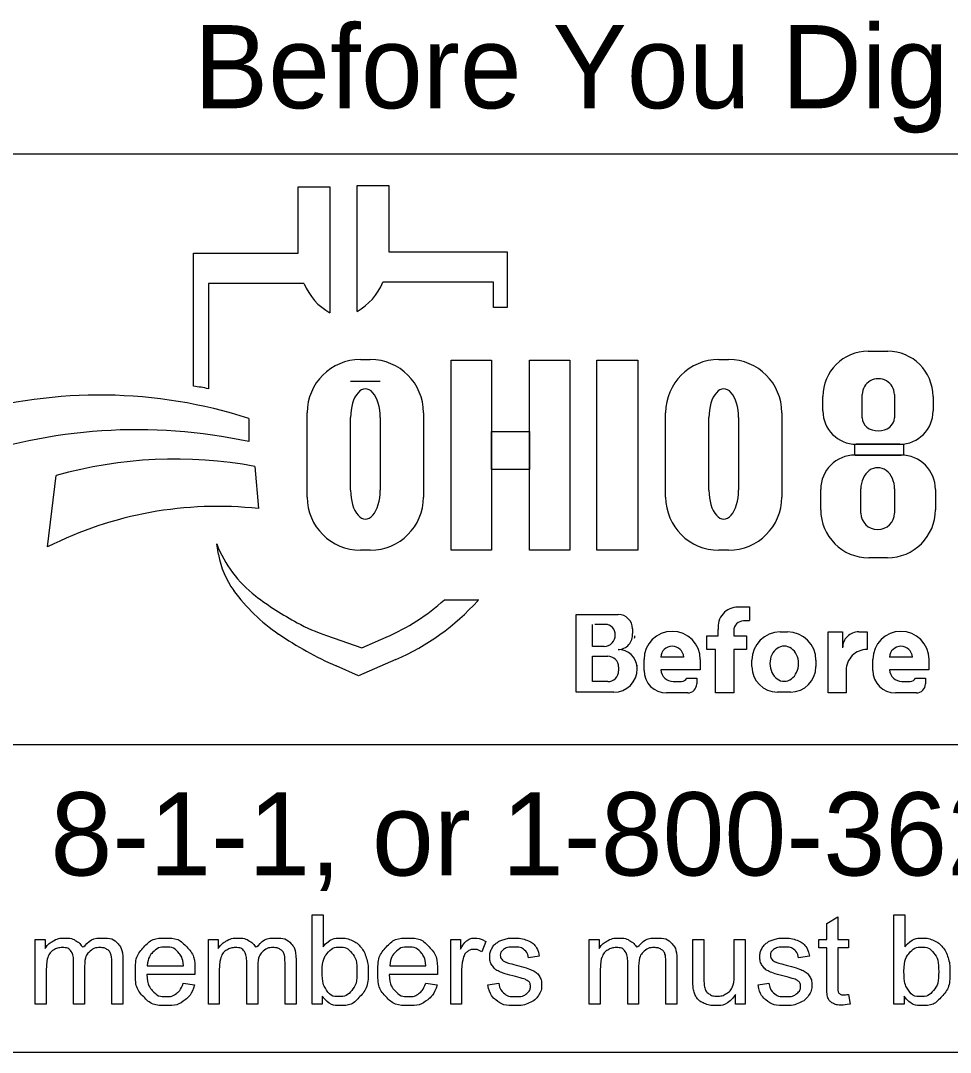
# Model space of a CAD drawing. Extents: x 0 to 34, y 0 to 22.
# Drawn here: x 3.267 to 4.831, y 2.143 to 3.88 of the extents above; entities that cross this region are included whole.
import ezdxf

# ---------------------------------------------------------------- set-up
doc = ezdxf.new("R2010")
doc.units = 0
doc.layers.add('SH_Data', color=7, linetype='Continuous')
doc.layers.add('SH_Text', color=7, linetype='Continuous')

msp = doc.modelspace()

# ---------------------------------------------------------------- linework, layer by layer
at = {"layer": 'SH_Data'}
for p, q in [((2.3775, 3.6553), (6.6275, 3.6553)), ((6.6275, 2.6607), (2.3775, 2.6607)), ((6.6275, 2.1428), (2.3775, 2.1428))]:
    msp.add_line(p, q, dxfattribs=at)
at = {"layer": 'SH_Text'}
for p, q in [((3.7335, 3.4883), (3.7335, 3.5998)), ((3.7335, 3.5998), (3.7872, 3.5998)), ((3.7872, 3.5998), (3.7872, 3.3877)), ((3.8329, 3.39), (3.8329, 3.6021)), ((3.8329, 3.6021), (3.8865, 3.6021)), ((3.8865, 3.6021), (3.8865, 3.4906)), ((3.5576, 3.2644), (3.5576, 3.4883)), ((3.5576, 3.4883), (3.7335, 3.4883)), ((3.8865, 3.4906), (4.0857, 3.4906)), ((4.0857, 3.4906), (4.0857, 3.3968)), ((4.0625, 3.4392), (3.8761, 3.4392)), ((4.0625, 3.3968), (4.0625, 3.4392)), ((3.5828, 3.4369), (3.5828, 3.26)), ((3.7439, 3.4369), (3.5828, 3.4369)), ((4.0857, 3.3968), (4.0625, 3.3968)), ((4.6931, 3.3231), (4.7258, 3.3231)), ((3.8385, 3.3091), (3.8551, 3.3091)), ((4.4416, 3.3091), (4.4581, 3.3091)), ((3.8718, 3.2721), (3.822, 3.2721)), ((4.683, 3.2111), (4.683, 3.2504)), ((4.7371, 3.2504), (4.7371, 3.2111)), ((4.6168, 3.2225), (4.6168, 3.2468)), ((4.8022, 3.2468), (4.8022, 3.2225)), ((3.7491, 3.0776), (3.7491, 3.2196)), ((3.9445, 3.2196), (3.9445, 3.0776)), ((4.3521, 3.0776), (4.3521, 3.2196)), ((4.5476, 3.2196), (4.5476, 3.0776)), ((3.6509, 3.2097), (3.6509, 3.1709)), ((3.822, 3.089), (3.822, 3.2114)), ((3.8718, 3.2114), (3.8718, 3.089)), ((4.425, 3.089), (4.425, 3.2114)), ((4.4748, 3.2114), (4.4748, 3.089)), ((4.7462, 3.1665), (4.6728, 3.1665)), ((4.671, 3.1482), (4.7483, 3.1482)), ((3.6608, 3.1291), (3.6671, 3.0582)), ((3.312, 2.9936), (3.3267, 3.1137)), ((4.6131, 3.0563), (4.6131, 3.0903)), ((4.6806, 3.0503), (4.6806, 3.0912)), ((4.7374, 3.0912), (4.7374, 3.0503)), ((4.8062, 3.0903), (4.8062, 3.0563)), ((3.5997, 2.9807), (3.5967, 2.9986)), ((3.8551, 2.9882), (3.8385, 2.9882)), ((4.4581, 2.9882), (4.4416, 2.9882)), ((4.7252, 2.9753), (4.6941, 2.9753)), ((3.98, 2.9048), (4.0375, 2.9048)), ((4.4739, 2.8926), (4.4934, 2.8926)), ((4.4934, 2.8926), (4.4934, 2.8696)), ((4.2013, 2.749), (4.2013, 2.8798)), ((4.2013, 2.8798), (4.2725, 2.8798)), ((4.4934, 2.8691), (4.4832, 2.8691)), ((4.2293, 2.8263), (4.2293, 2.8632)), ((4.2545, 2.8632), (4.2332, 2.8632)), ((4.2963, 2.856), (4.2963, 2.8481)), ((4.4406, 2.8442), (4.4406, 2.8546)), ((4.4667, 2.8526), (4.4667, 2.8442)), ((4.5451, 2.8508), (4.5573, 2.8508)), ((4.6254, 2.7478), (4.6254, 2.8505)), ((4.6254, 2.8505), (4.6499, 2.8505)), ((4.6499, 2.8505), (4.6499, 2.8237)), ((4.6772, 2.8505), (4.691, 2.8505)), ((4.691, 2.8505), (4.691, 2.8209)), ((3.7816, 2.8444), (3.841, 2.8239)), ((3.841, 2.8239), (3.8821, 2.8417)), ((4.4213, 2.8212), (4.4213, 2.8442)), ((4.4213, 2.8442), (4.4406, 2.8442)), ((4.4667, 2.8442), (4.4883, 2.8442)), ((4.4883, 2.8442), (4.4883, 2.8212)), ((4.2487, 2.8263), (4.2293, 2.8263)), ((4.4362, 2.8212), (4.4213, 2.8212)), ((4.4362, 2.7478), (4.4362, 2.8212)), ((4.4883, 2.8212), (4.4667, 2.8212)), ((4.4667, 2.8212), (4.4667, 2.7478)), ((3.8983, 2.8044), (3.835, 2.7769)), ((4.2293, 2.7669), (4.2293, 2.8097)), ((4.2293, 2.8097), (4.2548, 2.8097)), ((4.3159, 2.7858), (4.3159, 2.8042)), ((4.3824, 2.8082), (4.3439, 2.8082)), ((4.4104, 2.8042), (4.4104, 2.7866)), ((4.4973, 2.7922), (4.4973, 2.8029)), ((4.6051, 2.8029), (4.6051, 2.7922)), ((4.7008, 2.7858), (4.7008, 2.8042)), ((4.7674, 2.8082), (4.7288, 2.8082)), ((4.7953, 2.8042), (4.7953, 2.7866)), ((3.835, 2.7769), (3.7976, 2.7934)), ((4.2729, 2.7916), (4.2729, 2.7853)), ((4.3043, 2.7887), (4.3043, 2.7884)), ((4.4104, 2.7866), (4.344, 2.7866)), ((4.6559, 2.786), (4.6559, 2.7478)), ((4.7953, 2.7866), (4.7289, 2.7866)), ((4.2546, 2.7669), (4.2293, 2.7669)), ((4.3649, 2.7673), (4.379, 2.7673)), ((4.3876, 2.7729), (4.4045, 2.7729)), ((4.4045, 2.7729), (4.4045, 2.7631)), ((4.7498, 2.7673), (4.7639, 2.7673)), ((4.7725, 2.7729), (4.7894, 2.7729)), ((4.7894, 2.7729), (4.7894, 2.7631)), ((4.265, 2.749), (4.2013, 2.749)), ((4.3892, 2.7478), (4.3538, 2.7478)), ((4.4667, 2.7478), (4.4362, 2.7478)), ((4.5623, 2.7494), (4.5401, 2.7494)), ((4.6559, 2.7478), (4.6254, 2.7478)), ((4.7742, 2.7478), (4.7388, 2.7478))]:
    msp.add_line(p, q, dxfattribs=at)
for points in [[(3.991, 3.3081), (4.0589, 3.3081), (4.0589, 2.9881), (3.991, 2.9881)], [(4.1231, 3.3081), (4.1911, 3.3081), (4.1911, 2.9881), (4.1231, 2.9881)], [(4.2364, 3.3081), (4.3052, 3.3081), (4.3052, 2.9881), (4.2364, 2.9881)], [(4.0589, 3.1882), (4.1231, 3.1882), (4.1231, 3.1242), (4.0589, 3.1242)], [(4.6706, 3.1665), (4.7523, 3.1665), (4.7523, 3.1481), (4.6706, 3.1481)]]:
    msp.add_lwpolyline(points, close=True, dxfattribs=at)
for points in [[(3.7743, 2.2239), (3.7573, 2.2239), (3.7573, 2.3741), (3.7757, 2.3741), (3.7757, 2.3206)], [(4.6233, 2.2558), (4.6233, 2.3185), (4.6097, 2.3185), (4.6097, 2.3328), (4.6233, 2.3328), (4.6233, 2.3597), (4.6417, 2.3708), (4.6417, 2.3328), (4.6601, 2.3328), (4.6601, 2.3185), (4.6417, 2.3185), (4.6417, 2.2547)], [(4.7534, 2.2239), (4.7363, 2.2239), (4.7363, 2.3741), (4.7548, 2.3741), (4.7548, 2.3206)], [(3.2912, 2.2239), (3.2912, 2.3328), (3.3077, 2.3328), (3.3077, 2.3174)], [(3.5826, 2.2239), (3.5826, 2.3328), (3.5991, 2.3328), (3.5991, 2.3174)], [(3.9904, 2.2239), (3.9904, 2.3328), (4.007, 2.3328), (4.007, 2.3163)], [(4.0495, 2.3293), (4.043, 2.3122)], [(4.2236, 2.2239), (4.2236, 2.3328), (4.2401, 2.3328), (4.2401, 2.3174)], [(4.3979, 2.2654), (4.3979, 2.3328), (4.4164, 2.3328), (4.4164, 2.2724)], [(4.4676, 2.2745), (4.4676, 2.3328), (4.4861, 2.3328), (4.4861, 2.2239), (4.4696, 2.2239)], [(3.3743, 2.2871), (3.3743, 2.2239), (3.3559, 2.2239), (3.3559, 2.2946)], [(3.4388, 2.2986), (3.4388, 2.2239), (3.4203, 2.2239), (3.4203, 2.2924)], [(3.6657, 2.2871), (3.6657, 2.2239), (3.6473, 2.2239), (3.6473, 2.2946)], [(3.7301, 2.2986), (3.7301, 2.2239), (3.7117, 2.2239), (3.7117, 2.2924)], [(4.1394, 2.3046), (4.1213, 2.3022)], [(4.3067, 2.2871), (4.3067, 2.2239), (4.2883, 2.2239), (4.2883, 2.2946)], [(4.3711, 2.2986), (4.3711, 2.2239), (4.3527, 2.2239), (4.3527, 2.2924)], [(4.594, 2.3046), (4.5759, 2.3022)], [(3.3097, 2.2803), (3.3097, 2.2239), (3.2912, 2.2239)], [(3.4799, 2.2887), (3.5406, 2.2887)], [(3.601, 2.2803), (3.601, 2.2239), (3.5826, 2.2239)], [(3.8879, 2.2887), (3.9486, 2.2887)], [(4.0088, 2.2809), (4.0088, 2.2239), (3.9904, 2.2239)], [(4.242, 2.2803), (4.242, 2.2239), (4.2236, 2.2239)], [(3.56, 2.2736), (3.4788, 2.2736)], [(3.5404, 2.2591), (3.5595, 2.2567)], [(3.968, 2.2736), (3.8868, 2.2736)], [(3.9484, 2.2591), (3.9675, 2.2567)], [(4.053, 2.2564), (4.0712, 2.2593)], [(4.5076, 2.2564), (4.5258, 2.2593)], [(3.7743, 2.2375), (3.7743, 2.2239)], [(4.4696, 2.2239), (4.4696, 2.24)], [(4.6601, 2.2404), (4.6628, 2.2241)], [(4.7534, 2.2375), (4.7534, 2.2239)]]:
    msp.add_lwpolyline(points, dxfattribs=at)
for centre, radius, start, end in [((3.7847, 3.476), 0.0985, 299.2531, 338.0704), ((3.8353, 3.4736), 0.0985, 201.9296, 240.7469), ((4.6931, 3.2468), 0.0763, 90, 180), ((4.7258, 3.2468), 0.0763, 0, 90), ((3.8385, 3.2196), 0.0895, 90, 180), ((3.8551, 3.2196), 0.0895, 0, 90), ((4.4416, 3.2196), 0.0895, 90, 180), ((4.4581, 3.2196), 0.0895, 0, 90), ((3.3997, 2.4302), 0.8191, 72.1402, 106.3144), ((3.4295, 2.4554), 0.8191, 79.2074, 81.0007), ((4.6728, 3.2225), 0.056, 180, 270), ((4.7462, 3.2225), 0.056, 270, 0), ((3.4628, 2.2991), 0.8919, 77.8238, 109.8274), ((4.671, 3.0903), 0.0579, 90, 180), ((4.7483, 3.0903), 0.0579, 0, 90), ((3.5267, 2.4094), 0.7322, 79.44, 105.8467), ((3.8385, 3.0776), 0.0895, 180, 270), ((3.8551, 3.0776), 0.0895, 270, 0), ((4.4416, 3.0776), 0.0895, 180, 270), ((4.4581, 3.0776), 0.0895, 270, 0), ((3.5987, 2.4262), 0.6357, 83.8248, 116.8021), ((4.6941, 3.0563), 0.081, 180, 270), ((4.7252, 3.0563), 0.081, 270, 0), ((3.7841, 3.0707), 0.2008, 201.0457, 232.5314), ((3.741, 3.0048), 0.1433, 189.6817, 216.0884), ((3.8747, 3.1022), 0.3088, 216.0884, 235.7167), ((3.9766, 3.3219), 0.5173, 232.5314, 241.794), ((3.7387, 3.1722), 0.3602, 293.4582, 312.0712), ((3.7387, 3.1722), 0.401, 293.4582, 317.8286), ((4.4739, 2.859), 0.0335, 90, 187.5187), ((3.8914, 3.1631), 0.3371, 241.794, 250.9821), ((4.2725, 2.856), 0.0238, 0, 90), ((4.4832, 2.8526), 0.0165, 90, 180), ((4.2505, 2.8463), 0.0169, 357.8325, 90), ((4.3631, 2.8042), 0.0473, 0, 180), ((4.5451, 2.8029), 0.0478, 90, 180), ((4.5573, 2.8029), 0.0478, 0, 90), ((4.6768, 2.8237), 0.0269, 89.2449, 180), ((4.7481, 2.8042), 0.0473, 0, 180), ((4.0412, 3.3465), 0.6044, 235.7167, 246.2325), ((4.2487, 2.845), 0.0187, 270, 2.0582), ((4.2721, 2.8453), 0.0243, 270, 6.6529), ((4.2827, 2.8438), 0.0175, 347.4023, 0), ((4.2722, 2.7889), 0.0321, 4.0748, 90), ((4.3632, 2.8072), 0.0193, 2.9632, 177.0368), ((4.6908, 2.786), 0.0349, 89.6033, 180), ((4.7481, 2.8072), 0.0193, 2.9632, 177.0368), ((4.2548, 2.7916), 0.0181, 0, 90), ((4.2546, 2.7853), 0.0184, 270, 0), ((4.265, 2.7884), 0.0393, 270, 0), ((4.2714, 2.7887), 0.033, 0, 11.7502), ((4.3538, 2.7858), 0.038, 180, 270), ((4.3649, 2.7883), 0.021, 184.827, 270), ((4.5401, 2.7922), 0.0428, 180, 270), ((4.5623, 2.7922), 0.0428, 270, 0), ((4.7388, 2.7858), 0.038, 180, 270), ((4.7498, 2.7883), 0.021, 184.827, 270), ((4.379, 2.7767), 0.00938, 270, 335.9979), ((4.3892, 2.7631), 0.0152, 270, 0), ((4.7639, 2.7767), 0.00938, 270, 335.9979), ((4.7742, 2.7631), 0.0152, 270, 0)]:
    msp.add_arc(centre, radius, start, end, dxfattribs=at)
for centre, major_axis, ratio, start_param, end_param in [((4.71, 3.2504), (0.0271, 0), 0.969373, 0, 3.141593), ((3.8469, 3.2114), (0, 0.0484), 0.514403, 4.712389, 7.853982), ((4.4499, 3.2114), (0, 0.0484), 0.514403, 4.712389, 7.853982), ((4.71, 3.2111), (0.0271, 0), 0.818453, 3.141593, 6.283185), ((4.709, 3.0912), (0, 0.0358), 0.794529, 4.712389, 7.853982), ((3.8469, 3.089), (0, 0.0484), 0.514403, 1.570796, 4.712389), ((4.4499, 3.089), (0, 0.0484), 0.514403, 1.570796, 4.712389), ((4.709, 3.0503), (0.0284, 0), 0.959837, 3.141593, 6.283185), ((4.5517, 2.7976), (0, 0.029), 0.832186, 4.712389, 7.853982), ((4.5517, 2.7976), (0, 0.0302), 0.797287, 1.570796, 4.712389)]:
    msp.add_ellipse(centre, major_axis=major_axis, ratio=ratio, start_param=start_param, end_param=end_param, dxfattribs=at)
for points in [[(3.3077, 2.3174), (3.3128, 2.3254), (3.3214, 2.3303), (3.3299, 2.3352), (3.3407, 2.3352), (3.3528, 2.3352), (3.3606, 2.3301), (3.3683, 2.3251), (3.3715, 2.3161), (3.3844, 2.3352), (3.4051, 2.3352), (3.4213, 2.3352), (3.43, 2.3262), (3.4388, 2.3172), (3.4388, 2.2986)], [(3.5595, 2.2567), (3.555, 2.24), (3.5428, 2.2307), (3.5306, 2.2215), (3.5117, 2.2215), (3.4878, 2.2215), (3.4738, 2.2362), (3.4598, 2.2509), (3.4598, 2.2774), (3.4598, 2.3049), (3.474, 2.32), (3.4881, 2.3352), (3.5106, 2.3352), (3.5324, 2.3352), (3.5463, 2.3203), (3.5601, 2.3055), (3.5601, 2.2785), (3.5601, 2.2769), (3.56, 2.2736)], [(3.5991, 2.3174), (3.6042, 2.3254), (3.6127, 2.3303), (3.6212, 2.3352), (3.6321, 2.3352), (3.6442, 2.3352), (3.6519, 2.3301), (3.6597, 2.3251), (3.6628, 2.3161), (3.6758, 2.3352), (3.6965, 2.3352), (3.7127, 2.3352), (3.7214, 2.3262), (3.7301, 2.3172), (3.7301, 2.2986)], [(3.7757, 2.3206), (3.7874, 2.3352), (3.8055, 2.3352), (3.8155, 2.3352), (3.8245, 2.3311), (3.8335, 2.3271), (3.8392, 2.3198), (3.845, 2.3124), (3.8483, 2.3021), (3.8516, 2.2918), (3.8516, 2.28), (3.8516, 2.252), (3.8378, 2.2368), (3.8239, 2.2215), (3.8046, 2.2215), (3.7853, 2.2215), (3.7743, 2.2375)], [(3.9675, 2.2567), (3.963, 2.24), (3.9508, 2.2307), (3.9386, 2.2215), (3.9196, 2.2215), (3.8958, 2.2215), (3.8818, 2.2362), (3.8678, 2.2509), (3.8678, 2.2774), (3.8678, 2.3049), (3.882, 2.32), (3.8961, 2.3352), (3.9186, 2.3352), (3.9404, 2.3352), (3.9543, 2.3203), (3.9681, 2.3055), (3.9681, 2.2785), (3.9681, 2.2769), (3.968, 2.2736)], [(4.007, 2.3163), (4.0133, 2.3278), (4.0187, 2.3315), (4.0241, 2.3352), (4.0305, 2.3352), (4.0398, 2.3352), (4.0495, 2.3293)], [(4.0712, 2.2593), (4.0727, 2.2483), (4.0798, 2.2425), (4.0868, 2.2366), (4.0995, 2.2366), (4.1122, 2.2366), (4.1184, 2.2418), (4.1245, 2.247), (4.1245, 2.254), (4.1245, 2.2602), (4.1191, 2.2638), (4.1153, 2.2663), (4.1002, 2.2701), (4.0799, 2.2752), (4.072, 2.2789), (4.0642, 2.2827), (4.0601, 2.2893), (4.0561, 2.2959), (4.0561, 2.3038), (4.0561, 2.3111), (4.0594, 2.3173), (4.0628, 2.3235), (4.0685, 2.3276), (4.0728, 2.3308), (4.0803, 2.333), (4.0877, 2.3352), (4.0962, 2.3352), (4.109, 2.3352), (4.1187, 2.3315), (4.1284, 2.3278), (4.133, 2.3215), (4.1377, 2.3152), (4.1394, 2.3046)], [(4.2401, 2.3174), (4.2452, 2.3254), (4.2537, 2.3303), (4.2622, 2.3352), (4.2731, 2.3352), (4.2852, 2.3352), (4.2929, 2.3301), (4.3007, 2.3251), (4.3038, 2.3161), (4.3168, 2.3352), (4.3375, 2.3352), (4.3537, 2.3352), (4.3624, 2.3262), (4.3711, 2.3172), (4.3711, 2.2986)], [(4.5258, 2.2593), (4.5273, 2.2483), (4.5343, 2.2425), (4.5414, 2.2366), (4.554, 2.2366), (4.5668, 2.2366), (4.5729, 2.2418), (4.5791, 2.247), (4.5791, 2.254), (4.5791, 2.2602), (4.5736, 2.2638), (4.5698, 2.2663), (4.5548, 2.2701), (4.5345, 2.2752), (4.5266, 2.2789), (4.5188, 2.2827), (4.5147, 2.2893), (4.5107, 2.2959), (4.5107, 2.3038), (4.5107, 2.3111), (4.514, 2.3173), (4.5173, 2.3235), (4.5231, 2.3276), (4.5274, 2.3308), (4.5348, 2.333), (4.5423, 2.3352), (4.5508, 2.3352), (4.5636, 2.3352), (4.5733, 2.3315), (4.583, 2.3278), (4.5876, 2.3215), (4.5922, 2.3152), (4.594, 2.3046)], [(4.7548, 2.3206), (4.7664, 2.3352), (4.7846, 2.3352), (4.7946, 2.3352), (4.8036, 2.3311), (4.8125, 2.3271), (4.8183, 2.3198), (4.8241, 2.3124), (4.8274, 2.3021), (4.8306, 2.2918), (4.8306, 2.28), (4.8306, 2.252), (4.8168, 2.2368), (4.803, 2.2215), (4.7836, 2.2215), (4.7644, 2.2215), (4.7534, 2.2375)], [(3.3559, 2.2946), (3.3559, 2.3069), (3.3514, 2.313), (3.3469, 2.3191), (3.3366, 2.3191), (3.3288, 2.3191), (3.3222, 2.315), (3.3156, 2.311), (3.3126, 2.3031), (3.3097, 2.2952), (3.3097, 2.2803)], [(3.4203, 2.2924), (3.4203, 2.3035), (3.4185, 2.3083), (3.4168, 2.3132), (3.412, 2.3162), (3.4073, 2.3191), (3.401, 2.3191), (3.3895, 2.3191), (3.3819, 2.3115), (3.3743, 2.3039), (3.3743, 2.2871)], [(3.5406, 2.2887), (3.5394, 2.3025), (3.5337, 2.3094), (3.5249, 2.3201), (3.5108, 2.3201), (3.4981, 2.3201), (3.4894, 2.3115), (3.4808, 2.303), (3.4799, 2.2887)], [(3.6473, 2.2946), (3.6473, 2.3069), (3.6428, 2.313), (3.6383, 2.3191), (3.628, 2.3191), (3.6202, 2.3191), (3.6136, 2.315), (3.607, 2.311), (3.604, 2.3031), (3.601, 2.2952), (3.601, 2.2803)], [(3.7117, 2.2924), (3.7117, 2.3035), (3.7099, 2.3083), (3.7081, 2.3132), (3.7034, 2.3162), (3.6987, 2.3191), (3.6923, 2.3191), (3.6809, 2.3191), (3.6733, 2.3115), (3.6657, 2.3039), (3.6657, 2.2871)], [(3.7741, 2.2792), (3.7741, 2.2596), (3.7794, 2.2509), (3.7881, 2.2366), (3.8029, 2.2366), (3.815, 2.2366), (3.8238, 2.2471), (3.8326, 2.2576), (3.8326, 2.2784), (3.8326, 2.2998), (3.8241, 2.3099), (3.8157, 2.3201), (3.8038, 2.3201), (3.7917, 2.3201), (3.7829, 2.3096), (3.7741, 2.299), (3.7741, 2.2792)], [(3.9486, 2.2887), (3.9474, 2.3025), (3.9417, 2.3094), (3.9328, 2.3201), (3.9188, 2.3201), (3.9061, 2.3201), (3.8974, 2.3115), (3.8888, 2.303), (3.8879, 2.2887)], [(4.043, 2.3122), (4.0363, 2.3162), (4.0295, 2.3162), (4.0235, 2.3162), (4.0187, 2.3125), (4.0139, 2.3089), (4.0119, 2.3024), (4.0088, 2.2926), (4.0088, 2.2809)], [(4.1213, 2.3022), (4.1201, 2.3106), (4.1142, 2.3153), (4.1083, 2.3201), (4.0975, 2.3201), (4.0848, 2.3201), (4.0794, 2.3159), (4.0739, 2.3116), (4.0739, 2.306), (4.0739, 2.3024), (4.0762, 2.2995), (4.0785, 2.2966), (4.0833, 2.2946), (4.086, 2.2936), (4.0996, 2.2899), (4.1192, 2.2847), (4.1269, 2.2813), (4.1347, 2.278), (4.1391, 2.2717), (4.1435, 2.2653), (4.1435, 2.2559), (4.1435, 2.2467), (4.1381, 2.2386), (4.1327, 2.2304), (4.1226, 2.226), (4.1124, 2.2215), (4.0996, 2.2215), (4.0784, 2.2215), (4.0672, 2.2303), (4.0561, 2.2391), (4.053, 2.2564)], [(4.2883, 2.2946), (4.2883, 2.3069), (4.2838, 2.313), (4.2793, 2.3191), (4.269, 2.3191), (4.2612, 2.3191), (4.2546, 2.315), (4.248, 2.311), (4.245, 2.3031), (4.242, 2.2952), (4.242, 2.2803)], [(4.3527, 2.2924), (4.3527, 2.3035), (4.3509, 2.3083), (4.3491, 2.3132), (4.3444, 2.3162), (4.3397, 2.3191), (4.3333, 2.3191), (4.3219, 2.3191), (4.3143, 2.3115), (4.3067, 2.3039), (4.3067, 2.2871)], [(4.5759, 2.3022), (4.5747, 2.3106), (4.5688, 2.3153), (4.5629, 2.3201), (4.5521, 2.3201), (4.5394, 2.3201), (4.5339, 2.3159), (4.5285, 2.3116), (4.5285, 2.306), (4.5285, 2.3024), (4.5308, 2.2995), (4.533, 2.2966), (4.5378, 2.2946), (4.5406, 2.2936), (4.5542, 2.2899), (4.5737, 2.2847), (4.5815, 2.2813), (4.5893, 2.278), (4.5937, 2.2717), (4.5981, 2.2653), (4.5981, 2.2559), (4.5981, 2.2467), (4.5927, 2.2386), (4.5873, 2.2304), (4.5772, 2.226), (4.567, 2.2215), (4.5542, 2.2215), (4.5329, 2.2215), (4.5218, 2.2303), (4.5107, 2.2391), (4.5076, 2.2564)], [(4.7532, 2.2792), (4.7532, 2.2596), (4.7585, 2.2509), (4.7672, 2.2366), (4.782, 2.2366), (4.7941, 2.2366), (4.8029, 2.2471), (4.8116, 2.2576), (4.8116, 2.2784), (4.8116, 2.2998), (4.8032, 2.3099), (4.7948, 2.3201), (4.7828, 2.3201), (4.7708, 2.3201), (4.762, 2.3096), (4.7532, 2.299), (4.7532, 2.2792)], [(3.4788, 2.2736), (3.4799, 2.2557), (3.489, 2.2462), (3.4981, 2.2366), (3.5117, 2.2366), (3.5219, 2.2366), (3.5291, 2.242), (3.5362, 2.2473), (3.5404, 2.2591)], [(3.8868, 2.2736), (3.8879, 2.2557), (3.897, 2.2462), (3.9061, 2.2366), (3.9197, 2.2366), (3.9299, 2.2366), (3.937, 2.242), (3.9442, 2.2473), (3.9484, 2.2591)], [(4.4696, 2.24), (4.4569, 2.2215), (4.4351, 2.2215), (4.4255, 2.2215), (4.4171, 2.2252), (4.4088, 2.2289), (4.4047, 2.2345), (4.4007, 2.2401), (4.3991, 2.2482), (4.3979, 2.2536), (4.3979, 2.2654)], [(4.4164, 2.2724), (4.4164, 2.258), (4.4175, 2.253), (4.4192, 2.2457), (4.4249, 2.2416), (4.4305, 2.2374), (4.4388, 2.2374), (4.4471, 2.2374), (4.4543, 2.2417), (4.4616, 2.2459), (4.4646, 2.2533), (4.4676, 2.2606), (4.4676, 2.2745)], [(4.6628, 2.2241), (4.655, 2.2224), (4.6488, 2.2224), (4.6388, 2.2224), (4.6333, 2.2256), (4.6278, 2.2288), (4.6255, 2.234), (4.6233, 2.2392), (4.6233, 2.2558)], [(4.6417, 2.2547), (4.6417, 2.2468), (4.6427, 2.2445), (4.6436, 2.2423), (4.6458, 2.2409), (4.648, 2.2396), (4.6521, 2.2396), (4.6551, 2.2396), (4.6601, 2.2404)]]:
    msp.add_open_spline(points, degree=3, dxfattribs=at)

# ---------------------------------------------------------------- texts
for s, p in [('Before You Dig', (3.5583, 3.7321)), ('OHIO811, 8-1-1, or 1-800-362-2764', (2.422, 2.4406))]:
    msp.add_text(s, height=0.14, dxfattribs=at).set_placement(p)

doc.saveas('drawing.dxf')
